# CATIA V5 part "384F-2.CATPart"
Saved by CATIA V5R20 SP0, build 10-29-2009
Part number: 384F-2
Source: Unknown
Property "ARTICLENO": "384F-2"
Property "BOMINFO": "384F-2"
Property "CODE": "384F-2"
Property "CREATOR": "CADENAS GmbH"
Property "D1": "22.000"
Property "D2": "32.000"
Property "ELASTOMER": "Ø80-Ø100"
Property "K": "17.000"
Property "L": "74.000"
Property "L1": "10.000"
Property "L2": "34.000"
Property "LINA": "384F-2"
Property "M": "16.000"
Property "NB": "384F-2"
Property "NBSYN": "$CODE."
Property "NN": "384F"
Property "NT": "Pin for Elastomer Springs"
Property "R": "5.000"
Property "SUPPLIER": "CF"
Property "SW": "8.000"
Bounding box of the stored display mesh (mm): x -14.813 to 14.813, y 0 to 74, z -14.965 to 14.965
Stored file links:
  C:\Users\Raffaele\Desktop\3D X SITO CF\384F\GSB_OILLESS_M31102016074\CATIAV5\384F-2.CATPart
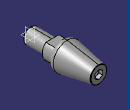
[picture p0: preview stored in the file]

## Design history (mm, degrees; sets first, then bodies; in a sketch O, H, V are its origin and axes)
Body1 "Geometry.1" (main body)
  Solid1 "384F-2.catpart": solid without history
